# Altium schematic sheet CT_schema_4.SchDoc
size 300 x 247 mm
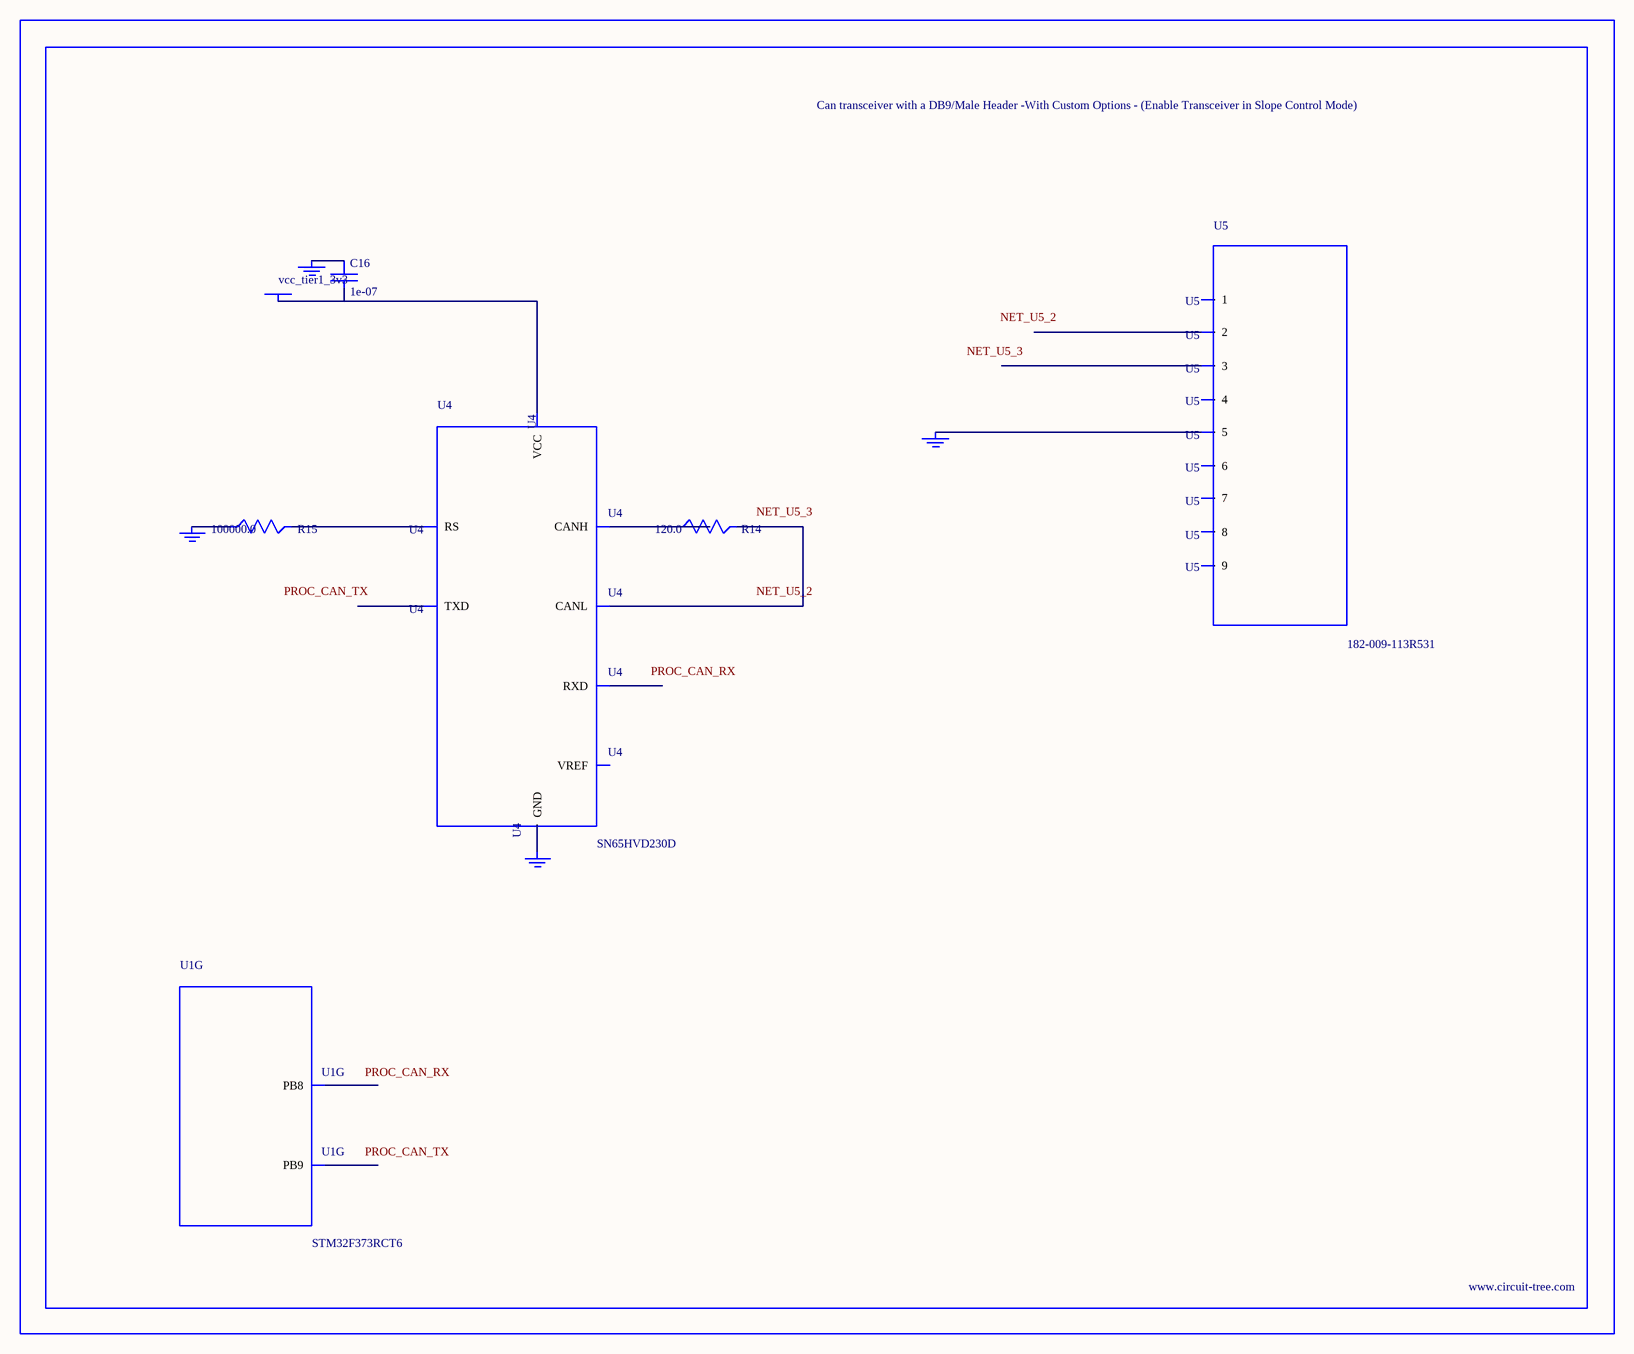
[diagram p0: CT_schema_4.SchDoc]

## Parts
BORDER3  (no value)
C16  1e-07  [C0402]
GND_INSTANCE_3_0  (no value)
GND_INSTANCE_3_1  (no value)
GND_INSTANCE_3_2  (no value)
GND_INSTANCE_3_3  (no value)
POWER_INSTANCE_3_0  vcc_tier1_3v3
R14  120.0  [R0603]
R15  100000.0  [R0603]
U1  STM32F373RCT6  [LQFP64]  (part G of 8)
U4  SN65HVD230D  [SOIC-8]
U5  182-009-113R531  [182-009-MALE]

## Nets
NetC16_1: C16.1 GND_INSTANCE_3_0.0(GND)
NetC16_2: C16.2 POWER_INSTANCE_3_0.0(PWR) U4.3(VCC)
NetGND_INSTANCE_3_1_0: GND_INSTANCE_3_1.0(GND) R15.1
NetGND_INSTANCE_3_2_0: GND_INSTANCE_3_2.0(GND) U4.2(GND)
NetGND_INSTANCE_3_3_0: GND_INSTANCE_3_3.0(GND) U5.5
NetR14_1: R14.1 U4.7(CANH)
NetR14_2: R14.2 U4.6(CANL)
NetR15_2: R15.2 U4.8(RS)

Not connected (* = marked no-connect by the designer): U1 61(PB8) 62(PB9); U4 1(TXD) 4(RXD) 5(VREF); U5 1 2 3 4 6 7 8 9

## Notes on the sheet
- Labels drawn without touching a wire or pin: NET_U5_2, NET_U5_3, PROC_CAN_RX, PROC_CAN_TX

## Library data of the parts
BORDER3 = BORDER_PAGE3
C16 = C0402C104K3RACTU
GND_INSTANCE_3_0-GND_INSTANCE_3_3 = GND
POWER_INSTANCE_3_0 = PWR
R14 = RC0603JR-07120RL
R15 = RC0603JR-07100KL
